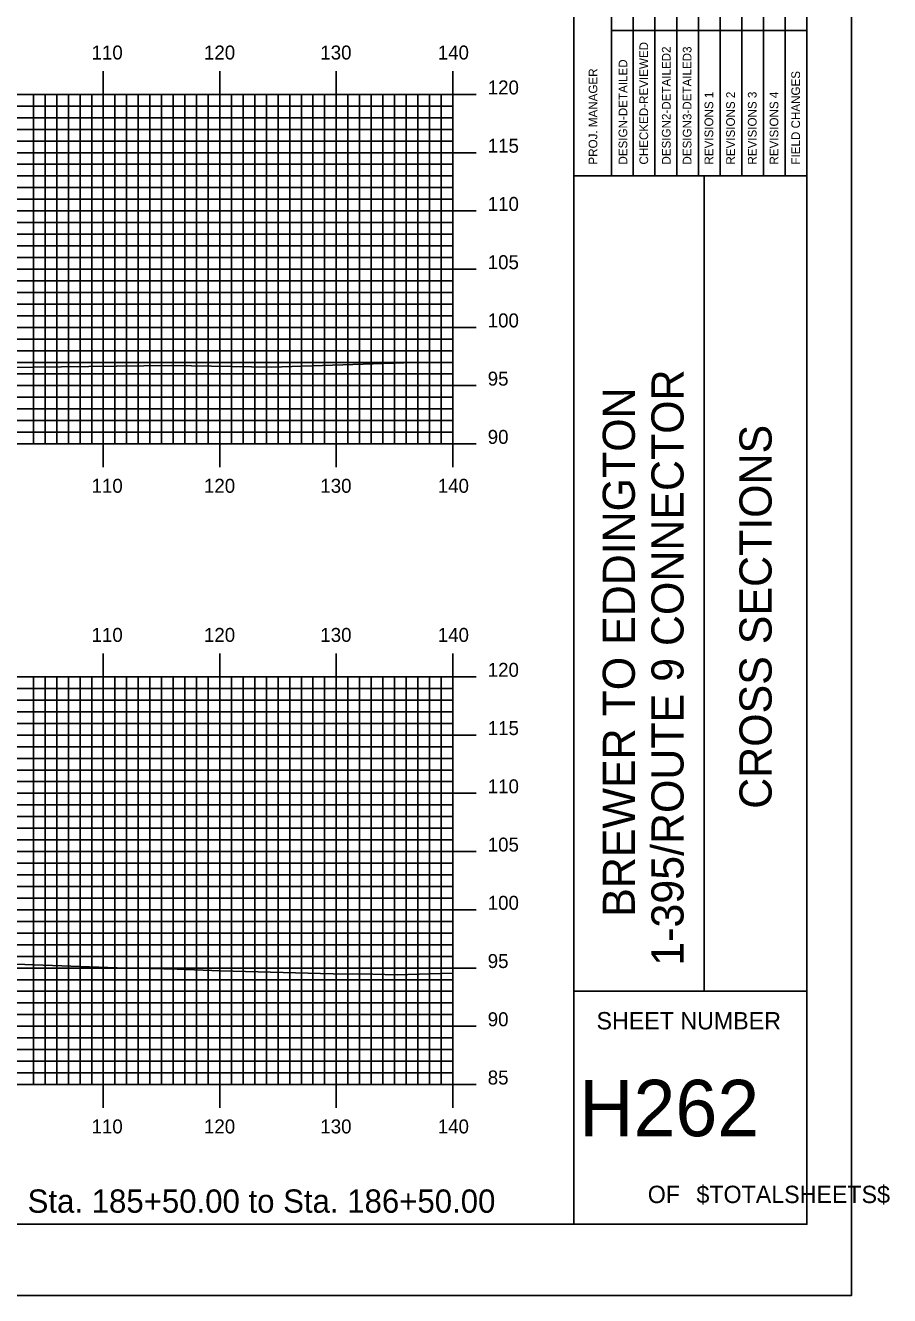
# Model space of a CAD drawing. Extents: x 1787369 to 1787713, y 442591 to 442811.
# Drawn here: x 1787638.4 to 1787712.6, y 442590.5 to 442699.6 of the extents above; entities that cross this region are included whole.
import ezdxf

# ---------------------------------------------------------------- set-up
doc = ezdxf.new("R2010")
doc.units = 0
for name, color, linetype in [('BORDER', 7, 'Continuous'), ('H_V ANNOTATION', 7, 'Continuous'), ('MAJOR', 7, 'Continuous'), ('MINOR', 7, 'Continuous'), ('PLOT BOUNDARY', 7, 'Continuous'), ('S_Roadway_Centerline', 7, 'Continuous')]:
    doc.layers.add(name, color=color, linetype=linetype)

msp = doc.modelspace()

# ---------------------------------------------------------------- linework, layer by layer
at = {"layer": 'BORDER'}
for p, q in [((1787685.5, 442596.67), (1787685.5, 442806.67)), ((1787685.5, 442686.67), (1787705.5, 442686.67)), ((1787696.69, 442616.67), (1787696.69, 442686.67)), ((1787685.5, 442616.67), (1787705.5, 442616.67))]:
    msp.add_line(p, q, dxfattribs=at)
msp.add_lwpolyline([(1787385.5, 442596.67), (1787705.5, 442596.67), (1787705.5, 442806.67), (1787385.5, 442806.67)], close=True, dxfattribs=at)
for points in [[(1787690.6, 442686.68), (1787690.6, 442721.67)], [(1787692.46, 442721.67), (1787692.46, 442686.68)], [(1787694.33, 442686.68), (1787694.33, 442721.67)], [(1787696.19, 442686.68), (1787696.19, 442721.67)], [(1787698.05, 442686.68), (1787698.05, 442721.67)], [(1787699.92, 442686.68), (1787699.92, 442721.67)], [(1787701.78, 442686.68), (1787701.78, 442721.67)], [(1787703.64, 442686.68), (1787703.64, 442721.67)], [(1787688.74, 442686.68), (1787688.74, 442720.26)], [(1787688.73, 442699.17), (1787705.5, 442699.17)]]:
    msp.add_lwpolyline(points, dxfattribs=at)
at = {"layer": 'MAJOR'}
for p, q in [((1787645.1, 442695.67), (1787645.1, 442693.67)), ((1787655.1, 442695.67), (1787655.1, 442693.67)), ((1787665.1, 442695.67), (1787665.1, 442693.67)), ((1787675.1, 442695.67), (1787675.1, 442693.67)), ((1787395.1, 442693.67), (1787675.1, 442693.67)), ((1787395.1, 442693.67), (1787675.1, 442693.67)), ((1787645.1, 442663.67), (1787645.1, 442693.67)), ((1787655.1, 442663.67), (1787655.1, 442693.67)), ((1787665.1, 442663.67), (1787665.1, 442693.67)), ((1787677.11, 442693.67), (1787673.1, 442693.67)), ((1787675.1, 442663.67), (1787675.1, 442693.67)), ((1787675.1, 442663.67), (1787675.1, 442693.67)), ((1787395.1, 442688.67), (1787675.1, 442688.67)), ((1787677.11, 442688.67), (1787673.1, 442688.67)), ((1787395.1, 442683.67), (1787675.1, 442683.67)), ((1787677.11, 442683.67), (1787673.1, 442683.67)), ((1787395.1, 442678.67), (1787675.1, 442678.67)), ((1787677.11, 442678.67), (1787673.1, 442678.67)), ((1787395.1, 442673.67), (1787675.1, 442673.67)), ((1787677.11, 442673.67), (1787673.1, 442673.67)), ((1787395.1, 442668.67), (1787675.1, 442668.67)), ((1787677.11, 442668.67), (1787673.1, 442668.67)), ((1787395.1, 442663.67), (1787675.1, 442663.67)), ((1787395.1, 442663.67), (1787675.1, 442663.67)), ((1787645.1, 442661.66), (1787645.1, 442663.67)), ((1787655.1, 442661.66), (1787655.1, 442663.67)), ((1787665.1, 442661.66), (1787665.1, 442663.67)), ((1787677.11, 442663.67), (1787673.1, 442663.67)), ((1787675.1, 442661.66), (1787675.1, 442663.67)), ((1787645.1, 442645.67), (1787645.1, 442643.67)), ((1787655.1, 442645.67), (1787655.1, 442643.67)), ((1787665.1, 442645.67), (1787665.1, 442643.67)), ((1787675.1, 442645.67), (1787675.1, 442643.67)), ((1787395.1, 442643.67), (1787675.1, 442643.67)), ((1787395.1, 442643.67), (1787675.1, 442643.67)), ((1787645.1, 442608.67), (1787645.1, 442643.67)), ((1787655.1, 442608.67), (1787655.1, 442643.67)), ((1787665.1, 442608.67), (1787665.1, 442643.67)), ((1787677.11, 442643.67), (1787673.1, 442643.67)), ((1787675.1, 442608.67), (1787675.1, 442643.67)), ((1787675.1, 442608.67), (1787675.1, 442643.67)), ((1787395.1, 442638.67), (1787675.1, 442638.67)), ((1787677.11, 442638.67), (1787673.1, 442638.67)), ((1787395.1, 442633.67), (1787675.1, 442633.67)), ((1787677.11, 442633.67), (1787673.1, 442633.67)), ((1787395.1, 442628.67), (1787675.1, 442628.67)), ((1787677.11, 442628.67), (1787673.1, 442628.67)), ((1787395.1, 442623.67), (1787675.1, 442623.67)), ((1787677.11, 442623.67), (1787673.1, 442623.67)), ((1787395.1, 442618.67), (1787675.1, 442618.67)), ((1787677.11, 442618.67), (1787673.1, 442618.67)), ((1787395.1, 442613.67), (1787675.1, 442613.67)), ((1787677.11, 442613.67), (1787673.1, 442613.67)), ((1787395.1, 442608.67), (1787675.1, 442608.67)), ((1787395.1, 442608.67), (1787675.1, 442608.67)), ((1787645.1, 442606.66), (1787645.1, 442608.67)), ((1787655.1, 442606.66), (1787655.1, 442608.67)), ((1787665.1, 442606.66), (1787665.1, 442608.67)), ((1787677.11, 442608.67), (1787673.1, 442608.67)), ((1787675.1, 442606.66), (1787675.1, 442608.67))]:
    msp.add_line(p, q, dxfattribs=at)
at = {"layer": 'MINOR'}
for p, q in [((1787639.1, 442663.67), (1787639.1, 442693.67)), ((1787640.1, 442663.67), (1787640.1, 442693.67)), ((1787641.1, 442663.67), (1787641.1, 442693.67)), ((1787642.1, 442663.67), (1787642.1, 442693.67)), ((1787643.1, 442663.67), (1787643.1, 442693.67)), ((1787644.1, 442663.67), (1787644.1, 442693.67)), ((1787646.1, 442663.67), (1787646.1, 442693.67)), ((1787647.1, 442663.67), (1787647.1, 442693.67)), ((1787648.1, 442663.67), (1787648.1, 442693.67)), ((1787649.1, 442663.67), (1787649.1, 442693.67)), ((1787650.1, 442663.67), (1787650.1, 442693.67)), ((1787651.1, 442663.67), (1787651.1, 442693.67)), ((1787652.1, 442663.67), (1787652.1, 442693.67)), ((1787653.1, 442663.67), (1787653.1, 442693.67)), ((1787654.1, 442663.67), (1787654.1, 442693.67)), ((1787656.1, 442663.67), (1787656.1, 442693.67)), ((1787657.1, 442663.67), (1787657.1, 442693.67)), ((1787658.1, 442663.67), (1787658.1, 442693.67)), ((1787659.1, 442663.67), (1787659.1, 442693.67)), ((1787660.1, 442663.67), (1787660.1, 442693.67)), ((1787661.1, 442663.67), (1787661.1, 442693.67)), ((1787662.1, 442663.67), (1787662.1, 442693.67)), ((1787663.1, 442663.67), (1787663.1, 442693.67)), ((1787664.1, 442663.67), (1787664.1, 442693.67)), ((1787666.1, 442663.67), (1787666.1, 442693.67)), ((1787667.1, 442663.67), (1787667.1, 442693.67)), ((1787668.1, 442663.67), (1787668.1, 442693.67)), ((1787669.1, 442663.67), (1787669.1, 442693.67)), ((1787670.1, 442663.67), (1787670.1, 442693.67)), ((1787671.1, 442663.67), (1787671.1, 442693.67)), ((1787672.1, 442663.67), (1787672.1, 442693.67)), ((1787673.1, 442663.67), (1787673.1, 442693.67)), ((1787674.1, 442663.67), (1787674.1, 442693.67)), ((1787395.1, 442692.67), (1787675.1, 442692.67)), ((1787395.1, 442691.67), (1787675.1, 442691.67)), ((1787675.1, 442692.67), (1787673.1, 442692.67)), ((1787675.1, 442691.67), (1787673.1, 442691.67)), ((1787395.1, 442690.67), (1787675.1, 442690.67)), ((1787675.1, 442690.67), (1787673.1, 442690.67)), ((1787395.1, 442689.67), (1787675.1, 442689.67)), ((1787675.1, 442689.67), (1787673.1, 442689.67)), ((1787395.1, 442687.67), (1787675.1, 442687.67)), ((1787675.1, 442687.67), (1787673.1, 442687.67)), ((1787395.1, 442686.67), (1787675.1, 442686.67)), ((1787675.1, 442686.67), (1787673.1, 442686.67)), ((1787395.1, 442685.67), (1787675.1, 442685.67)), ((1787675.1, 442685.67), (1787673.1, 442685.67)), ((1787395.1, 442684.67), (1787675.1, 442684.67)), ((1787675.1, 442684.67), (1787673.1, 442684.67)), ((1787395.1, 442682.67), (1787675.1, 442682.67)), ((1787675.1, 442682.67), (1787673.1, 442682.67)), ((1787395.1, 442681.67), (1787675.1, 442681.67)), ((1787675.1, 442681.67), (1787673.1, 442681.67)), ((1787395.1, 442680.67), (1787675.1, 442680.67)), ((1787395.1, 442679.67), (1787675.1, 442679.67)), ((1787675.1, 442680.67), (1787673.1, 442680.67)), ((1787675.1, 442679.67), (1787673.1, 442679.67)), ((1787395.1, 442677.67), (1787675.1, 442677.67)), ((1787675.1, 442677.67), (1787673.1, 442677.67)), ((1787395.1, 442676.67), (1787675.1, 442676.67)), ((1787675.1, 442676.67), (1787673.1, 442676.67)), ((1787395.1, 442675.67), (1787675.1, 442675.67)), ((1787675.1, 442675.67), (1787673.1, 442675.67)), ((1787395.1, 442674.67), (1787675.1, 442674.67)), ((1787675.1, 442674.67), (1787673.1, 442674.67)), ((1787395.1, 442672.67), (1787675.1, 442672.67)), ((1787675.1, 442672.67), (1787673.1, 442672.67)), ((1787395.1, 442671.67), (1787675.1, 442671.67)), ((1787675.1, 442671.67), (1787673.1, 442671.67)), ((1787395.1, 442670.67), (1787675.1, 442670.67)), ((1787675.1, 442670.67), (1787673.1, 442670.67)), ((1787395.1, 442669.67), (1787675.1, 442669.67)), ((1787675.1, 442669.67), (1787673.1, 442669.67)), ((1787395.1, 442667.67), (1787675.1, 442667.67)), ((1787675.1, 442667.67), (1787673.1, 442667.67)), ((1787395.1, 442666.67), (1787675.1, 442666.67)), ((1787675.1, 442666.67), (1787673.1, 442666.67)), ((1787395.1, 442665.67), (1787675.1, 442665.67)), ((1787675.1, 442665.67), (1787673.1, 442665.67)), ((1787395.1, 442664.67), (1787675.1, 442664.67)), ((1787675.1, 442664.67), (1787673.1, 442664.67)), ((1787639.1, 442608.67), (1787639.1, 442643.67)), ((1787640.1, 442608.67), (1787640.1, 442643.67)), ((1787641.1, 442608.67), (1787641.1, 442643.67)), ((1787642.1, 442608.67), (1787642.1, 442643.67)), ((1787643.1, 442608.67), (1787643.1, 442643.67)), ((1787644.1, 442608.67), (1787644.1, 442643.67)), ((1787646.1, 442608.67), (1787646.1, 442643.67)), ((1787647.1, 442608.67), (1787647.1, 442643.67)), ((1787648.1, 442608.67), (1787648.1, 442643.67)), ((1787649.1, 442608.67), (1787649.1, 442643.67)), ((1787650.1, 442608.67), (1787650.1, 442643.67)), ((1787651.1, 442608.67), (1787651.1, 442643.67)), ((1787652.1, 442608.67), (1787652.1, 442643.67)), ((1787653.1, 442608.67), (1787653.1, 442643.67)), ((1787654.1, 442608.67), (1787654.1, 442643.67)), ((1787656.1, 442608.67), (1787656.1, 442643.67)), ((1787657.1, 442608.67), (1787657.1, 442643.67)), ((1787658.1, 442608.67), (1787658.1, 442643.67)), ((1787659.1, 442608.67), (1787659.1, 442643.67)), ((1787660.1, 442608.67), (1787660.1, 442643.67)), ((1787661.1, 442608.67), (1787661.1, 442643.67)), ((1787662.1, 442608.67), (1787662.1, 442643.67)), ((1787663.1, 442608.67), (1787663.1, 442643.67)), ((1787664.1, 442608.67), (1787664.1, 442643.67)), ((1787666.1, 442608.67), (1787666.1, 442643.67)), ((1787667.1, 442608.67), (1787667.1, 442643.67)), ((1787668.1, 442608.67), (1787668.1, 442643.67)), ((1787669.1, 442608.67), (1787669.1, 442643.67)), ((1787670.1, 442608.67), (1787670.1, 442643.67)), ((1787671.1, 442608.67), (1787671.1, 442643.67)), ((1787672.1, 442608.67), (1787672.1, 442643.67)), ((1787673.1, 442608.67), (1787673.1, 442643.67)), ((1787674.1, 442608.67), (1787674.1, 442643.67)), ((1787395.1, 442642.67), (1787675.1, 442642.67)), ((1787675.1, 442642.67), (1787673.1, 442642.67)), ((1787395.1, 442641.67), (1787675.1, 442641.67)), ((1787675.1, 442641.67), (1787673.1, 442641.67)), ((1787395.1, 442640.67), (1787675.1, 442640.67)), ((1787675.1, 442640.67), (1787673.1, 442640.67)), ((1787395.1, 442639.67), (1787675.1, 442639.67)), ((1787675.1, 442639.67), (1787673.1, 442639.67)), ((1787395.1, 442637.67), (1787675.1, 442637.67)), ((1787675.1, 442637.67), (1787673.1, 442637.67)), ((1787395.1, 442636.67), (1787675.1, 442636.67)), ((1787675.1, 442636.67), (1787673.1, 442636.67)), ((1787395.1, 442635.67), (1787675.1, 442635.67)), ((1787675.1, 442635.67), (1787673.1, 442635.67)), ((1787395.1, 442634.67), (1787675.1, 442634.67)), ((1787675.1, 442634.67), (1787673.1, 442634.67)), ((1787395.1, 442632.67), (1787675.1, 442632.67)), ((1787675.1, 442632.67), (1787673.1, 442632.67)), ((1787395.1, 442631.67), (1787675.1, 442631.67)), ((1787395.1, 442630.67), (1787675.1, 442630.67)), ((1787675.1, 442631.67), (1787673.1, 442631.67)), ((1787675.1, 442630.67), (1787673.1, 442630.67)), ((1787395.1, 442629.67), (1787675.1, 442629.67)), ((1787675.1, 442629.67), (1787673.1, 442629.67)), ((1787395.1, 442627.67), (1787675.1, 442627.67)), ((1787675.1, 442627.67), (1787673.1, 442627.67)), ((1787395.1, 442626.67), (1787675.1, 442626.67)), ((1787675.1, 442626.67), (1787673.1, 442626.67)), ((1787395.1, 442625.67), (1787675.1, 442625.67)), ((1787675.1, 442625.67), (1787673.1, 442625.67)), ((1787395.1, 442624.67), (1787675.1, 442624.67)), ((1787675.1, 442624.67), (1787673.1, 442624.67)), ((1787395.1, 442622.67), (1787675.1, 442622.67)), ((1787675.1, 442622.67), (1787673.1, 442622.67)), ((1787395.1, 442621.67), (1787675.1, 442621.67)), ((1787675.1, 442621.67), (1787673.1, 442621.67)), ((1787395.1, 442620.67), (1787675.1, 442620.67)), ((1787675.1, 442620.67), (1787673.1, 442620.67)), ((1787395.1, 442619.67), (1787675.1, 442619.67)), ((1787675.1, 442619.67), (1787673.1, 442619.67)), ((1787395.1, 442617.67), (1787675.1, 442617.67)), ((1787675.1, 442617.67), (1787673.1, 442617.67)), ((1787395.1, 442616.67), (1787675.1, 442616.67)), ((1787675.1, 442616.67), (1787673.1, 442616.67)), ((1787395.1, 442615.67), (1787675.1, 442615.67)), ((1787675.1, 442615.67), (1787673.1, 442615.67)), ((1787395.1, 442614.67), (1787675.1, 442614.67)), ((1787675.1, 442614.67), (1787673.1, 442614.67)), ((1787395.1, 442612.67), (1787675.1, 442612.67)), ((1787675.1, 442612.67), (1787673.1, 442612.67)), ((1787395.1, 442611.67), (1787675.1, 442611.67)), ((1787675.1, 442611.67), (1787673.1, 442611.67)), ((1787395.1, 442610.67), (1787675.1, 442610.67)), ((1787675.1, 442610.67), (1787673.1, 442610.67)), ((1787395.1, 442609.67), (1787675.1, 442609.67)), ((1787675.1, 442609.67), (1787673.1, 442609.67))]:
    msp.add_line(p, q, dxfattribs=at)
at = {"layer": 'PLOT BOUNDARY'}
msp.add_lwpolyline([(1787369.32, 442590.55), (1787709.32, 442590.55), (1787709.32, 442810.55), (1787369.32, 442810.55)], close=True, dxfattribs=at)
at = {"layer": 'S_Roadway_Centerline'}
for points in [[(1787555.6, 442670.14), (1787572.15, 442669.78), (1787574.69, 442669.66), (1787578.43, 442669.77), (1787586.95, 442669.73), (1787591.41, 442669.67), (1787600.47, 442669.89), (1787611.42, 442670.29), (1787613.49, 442670.32), (1787624.76, 442670.49), (1787632.06, 442670.17), (1787643.85, 442670.32), (1787650.95, 442670.41), (1787659.55, 442670.25), (1787670.91, 442670.62), (1787671.69, 442670.65), (1787672.81, 442670.64), (1787675.1, 442670.68)], [(1787555.27, 442619.85), (1787566.74, 442619.43), (1787567.22, 442619.42), (1787586.59, 442619.47), (1787596.37, 442619.46), (1787603.97, 442619.39), (1787606.29, 442619.41), (1787613.92, 442619.31), (1787625.86, 442619.42), (1787626.43, 442619.41), (1787646.29, 442618.7), (1787649.11, 442618.62), (1787651.45, 442618.57), (1787655.15, 442618.43), (1787664.84, 442618.16), (1787668.25, 442618.14), (1787670.33, 442618.09), (1787671.24, 442618.11), (1787675.1, 442618.22)]]:
    msp.add_lwpolyline(points, dxfattribs=at)

# ---------------------------------------------------------------- texts
at = {"layer": 'BORDER'}
for s, height, p in [('CHECKED-REVIEWED', 0.7455, (1787691.87, 442687.65)), ('DESIGN2-DETAILED2', 0.7455, (1787693.8, 442687.65)), ('DESIGN3-DETAILED3', 0.7455, (1787695.59, 442687.65)), ('DESIGN-DETAILED', 0.7455, (1787690.08, 442687.65)), ('PROJ. MANAGER', 0.7455, (1787687.51, 442687.65)), ('FIELD CHANGES', 0.7455, (1787704.91, 442687.65)), ('REVISIONS 1', 0.7455, (1787697.46, 442687.65)), ('REVISIONS 2', 0.7455, (1787699.32, 442687.65)), ('REVISIONS 3', 0.7455, (1787701.18, 442687.65)), ('REVISIONS 4', 0.7455, (1787703.05, 442687.65)), ('1-395/ROUTE 9 CONNECTOR', 2.7557, (1787694.91, 442618.87)), ('BREWER TO EDDINGTON', 2.7557, (1787690.73, 442623.07)), ('CROSS SECTIONS', 2.7557, (1787702.47, 442632.34))]:
    msp.add_text(s, height=height, rotation=90, dxfattribs=at).set_placement(p)
for s, height, p in [('SHEET NUMBER', 1.4905, (1787687.44, 442613.4)), ('H262', 4.839, (1787685.94, 442604.23)), ('$TOTALSHEETS$', 1.4905, (1787696.02, 442598.49)), ('OF', 1.491, (1787691.84, 442598.49))]:
    msp.add_text(s, height=height, dxfattribs=at).set_placement(p)
at = {"layer": 'H_V ANNOTATION'}
for s, height, p in [('110', 1.2, (1787644.09, 442696.67)), ('120', 1.2, (1787653.74, 442696.67)), ('130', 1.2, (1787663.73, 442696.67)), ('140', 1.2, (1787673.81, 442696.67)), ('120', 1.2, (1787678.1, 442693.67)), ('115', 1.2, (1787678.1, 442688.67)), ('110', 1.2, (1787678.1, 442683.67)), ('105', 1.2, (1787678.1, 442678.67)), ('100', 1.2, (1787678.1, 442673.67)), ('95', 1.2, (1787678.1, 442668.67)), ('90', 1.2, (1787678.1, 442663.67)), ('110', 1.2, (1787644.09, 442659.47)), ('120', 1.2, (1787653.74, 442659.47)), ('130', 1.2, (1787663.73, 442659.47)), ('140', 1.2, (1787673.81, 442659.47)), ('110', 1.2, (1787644.09, 442646.67)), ('120', 1.2, (1787653.74, 442646.67)), ('130', 1.2, (1787663.73, 442646.67)), ('140', 1.2, (1787673.81, 442646.67)), ('120', 1.2, (1787678.1, 442643.67)), ('115', 1.2, (1787678.1, 442638.67)), ('110', 1.2, (1787678.1, 442633.67)), ('105', 1.2, (1787678.1, 442628.67)), ('100', 1.2, (1787678.1, 442623.67)), ('95', 1.2, (1787678.1, 442618.67)), ('90', 1.2, (1787678.1, 442613.67)), ('85', 1.2, (1787678.1, 442608.67)), ('110', 1.2, (1787644.09, 442604.47)), ('120', 1.2, (1787653.74, 442604.47)), ('130', 1.2, (1787663.73, 442604.47)), ('140', 1.2, (1787673.81, 442604.47)), ('Sta. 185+50.00 to Sta. 186+50.00', 2.0004, (1787638.6, 442597.66))]:
    msp.add_text(s, height=height, dxfattribs=at).set_placement(p)

doc.saveas('drawing.dxf')
